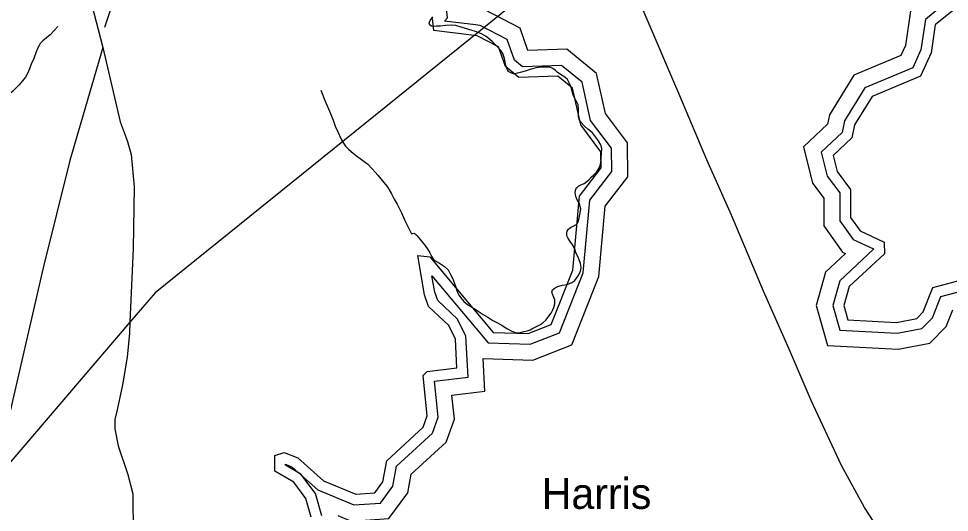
# Model space of a CAD drawing. Extents: x 2001466 to 2224147, y 644118 to 847247.
# Drawn here: x 2011540 to 2017291, y 677010 to 680062 of the extents above; entities that cross this region are included whole.
import ezdxf

# ---------------------------------------------------------------- set-up
doc = ezdxf.new("R2010")
doc.units = 0
for name, color, linetype in [('Exist Hydrographic Buffer Line', 7, 'Continuous'), ('Exist Hydrographic Lake Shore', 7, 'Continuous'), ('Exist Hydrographic Lake Shore Label', 7, 'Continuous'), ('Exist Hydrographic Misc Water Feature', 7, 'Continuous'), ('Exist Railroad Mainline', 7, 'Continuous'), ('Exist Road Non-System Type 51', 7, 'Continuous'), ('Exist Utilities Electrical Transmission Line', 7, 'Continuous')]:
    doc.layers.add(name, color=color, linetype=linetype)

msp = doc.modelspace()

# ---------------------------------------------------------------- linework, layer by layer
at = {"layer": 'Exist Hydrographic Buffer Line'}
for points in [[(2014363, 680022.7), (2014170.6, 680045.5), (2014189.4, 680065.8), (2014169, 680258.8), (2014072.9, 680448.3), (2013851.9, 680620.9), (2013847.9, 680695.5), (2013923.6, 680666.6), (2014089.2, 680466.7)], [(2017260.4, 680153.7), (2017142.7, 680057.2), (2017115.4, 679868.1), (2017064.1, 679757), (2016768.2, 679633.6), (2016643.2, 679430.8), (2016628, 679358.1), (2016498.9, 679236.6), (2016536.7, 679087.3), (2016614.4, 678984.4), (2016614.4, 678811.6), (2016695.5, 678697), (2016823, 678638.3), (2016823, 678636.6), (2016613.6, 678441.5), (2016570.9, 678288.6), (2016613.3, 678136.6), (2016968.3, 678117.6), (2017121.4, 678146.7), (2017186.1, 678212.7), (2017237.9, 678344.1), (2017449.4, 678400.7)], [(2014409.3, 677960.8), (2014717.5, 677949.8), (2014957.2, 678044.7), (2015125.2, 678468.1), (2015164.1, 678902.8), (2015303.7, 679084.4), (2015301.5, 679293.3), (2015165.5, 679474.4), (2015110.9, 679723), (2014927.8, 679872), (2014686.6, 679863.7), (2014638.7, 680002.9), (2014420.7, 680115), (2014374.6, 680120.5)], [(2017050.7, 680109.1), (2017020, 679896.3), (2016990.8, 679833.1), (2016701, 679712.2), (2016550.3, 679467.7), (2016538, 679408.5), (2016389.3, 679268.6), (2016446.1, 679043.9), (2016516, 678951.4), (2016516, 678780.3), (2016630.4, 678618.7), (2016649.8, 678609.7), (2016526.3, 678494.6), (2016468.7, 678288.7), (2016537.5, 678042), (2016974.9, 678018.7), (2017170.1, 678055.7), (2017270.4, 678158), (2017311.3, 678261.8)], [(2013413.9, 676988.9), (2013374.7, 677125.9), (2013284.4, 677246.2), (2013188.6, 677301.9), (2013188.6, 677307), (2013229.6, 677290.2), (2013387.6, 677149.2), (2013611.9, 677056.3), (2013774.8, 677066.8), (2013851.5, 677171.3), (2013875.3, 677295.4), (2014096.2, 677500.2), (2014131.9, 677597.6), (2014108.6, 677820.9), (2014316.6, 677846.4), (2014303.8, 678098.4), (2014251.5, 678204.1), (2014129.5, 678318.7), (2014110.7, 678371), (2014093.6, 678472.8), (2014441.4, 678058.1), (2014700.4, 678048.9), (2014881.4, 678120.6), (2015028.5, 678491.1), (2015068.6, 678940.1), (2015204.9, 679117.4), (2015203.5, 679260), (2015074, 679432.4), (2015022.1, 679668.3), (2014894.3, 679772.3), (2014652.3, 679764.1), (2014603.1, 679804.1), (2014558.5, 679933.5), (2014391.5, 680019.3), (2014363, 680022.7)], [(2013512.4, 676991), (2013595.4, 676956.6), (2013827, 676971.5), (2013944, 677130.9), (2013965.9, 677245.2), (2014180.5, 677444.1), (2014232.1, 677585.2), (2014216.5, 677735), (2014419.5, 677759.9), (2014409.3, 677960.8)]]:
    msp.add_lwpolyline(points, dxfattribs=at)
at = {"layer": 'Exist Hydrographic Lake Shore'}
for points in [[(2017329.1, 680125.2), (2017204, 680022.6), (2017179, 679849.3), (2017112.9, 679706.3), (2016812.9, 679581.2), (2016705.1, 679406.1), (2016688.1, 679324.4), (2016572, 679215.2), (2016597, 679116.3), (2016680.1, 679006.4), (2016680.1, 678832.5), (2016738.9, 678749.3), (2016888, 678680.6), (2016889, 678608.4), (2016671.9, 678406.1), (2016639.1, 678288.6), (2016663.9, 678199.6), (2016963.9, 678183.6), (2017088.9, 678207.3), (2017129.9, 678249.1), (2017189, 678398.9), (2017404.9, 678456.8)], [(2014355.3, 679957.6), (2014105, 679987.2), (2014097, 680062.9)], [(2013348, 676980.7), (2013315, 677096.2), (2013239.9, 677196.2), (2013123, 677264.2), (2013123, 677362.6), (2013181.1, 677381.1), (2013264.9, 677346.6), (2013423, 677205.6), (2013622.9, 677122.7), (2013740, 677130.3), (2013789.9, 677198.1), (2013814.9, 677328.9), (2014040, 677537.6), (2014065, 677605.9), (2014039, 677855.8), (2014064, 677881.6), (2014247.9, 677904.1), (2014238.9, 678081.5), (2014197.9, 678164.3), (2014073, 678281.7), (2014047, 678354.4), (2014006, 678598.1), (2014081, 678589.9), (2014472.9, 678122.7), (2014689, 678115), (2014830.9, 678171.2), (2014964, 678506.4), (2015005, 678964.9), (2015139.1, 679139.4), (2015138.1, 679237.8), (2015013, 679404.4), (2014963, 679631.9), (2014871.9, 679705.9), (2014630, 679697.7), (2014547.1, 679765), (2014505.1, 679887.2), (2014372, 679955.6), (2014355.3, 679957.6)]]:
    msp.add_lwpolyline(points, dxfattribs=at)
at = {"layer": 'Exist Hydrographic Misc Water Feature'}
for points in [[(2015112, 679115.3), (2015130.1, 679145.3), (2015138.1, 679173), (2015139.9, 679197.6), (2015142, 679231.2), (2015143.8, 679259), (2015136.4, 679281.4), (2015121.9, 679305.4), (2015103.6, 679331.2), (2015085.8, 679355.3), (2015057.7, 679378.9), (2015035.5, 679397.4), (2015015.7, 679419.1), (2015005.6, 679433.3), (2014999.7, 679455.6), (2014999.5, 679475.2), (2014999.5, 679501.5), (2014996.2, 679527.8), (2014987.4, 679549.3), (2014975.1, 679572.5), (2014965.2, 679590.8), (2014953.3, 679635.3), (2014944.1, 679660.1), (2014931, 679685), (2014915.2, 679699.2), (2014887.1, 679717.1), (2014867, 679730.6), (2014854.5, 679743.1), (2014840.7, 679754.1), (2014821.1, 679761), (2014789.1, 679762.5), (2014763, 679760.6), (2014729, 679754.7), (2014700.5, 679746.3), (2014669.7, 679737.9), (2014639.2, 679728.6), (2014605.1, 679720.3), (2014597.6, 679720.5), (2014580.9, 679726.5), (2014567, 679734.2), (2014560.8, 679744.9), (2014551, 679772.3), (2014541, 679815.9), (2014531.1, 679846.4), (2014520.9, 679863.1), (2014498.7, 679888.2), (2014464.7, 679920), (2014428.8, 679951.9), (2014400.7, 679968.1), (2014362.8, 679982), (2014320.7, 679994.3), (2014280.7, 680005.8), (2014240.6, 680019.7), (2014214.3, 680021.9), (2014176.6, 680019.4), (2014146.6, 680015.9), (2014122.7, 680014), (2014104.8, 680013.5), (2014090.7, 680015.4), (2014080.8, 680021.3), (2014076.7, 680033.7), (2014082.5, 680049.2), (2014098.5, 680073.4)], [(2011781.6, 680012.3), (2011759.6, 679988.1), (2011733.6, 679962.4), (2011711.7, 679943.9), (2011689.7, 679923.9), (2011673.5, 679907.9), (2011665.7, 679895.7), (2011657.7, 679881.9), (2011647.7, 679855.8), (2011633.7, 679815.2), (2011617.9, 679780.2), (2011606, 679751.7), (2011594, 679721.6), (2011582.1, 679699.7), (2011564, 679676.3), (2011542.1, 679652.2), (2011522.4, 679632), (2011502.3, 679611.9), (2011486.1, 679597.5), (2011466.2, 679579.8), (2011450.2, 679563.8), (2011440.4, 679551.6), (2011432.4, 679543.6), (2011426.6, 679538)], [(2013406, 679619.2), (2013434.1, 679551.3), (2013459.9, 679489.3), (2013470.2, 679465.3), (2013482.3, 679433.1), (2013496.2, 679397.5), (2013510.4, 679365.2), (2013532.3, 679315.6), (2013546.5, 679291.5), (2013560.4, 679273.1), (2013580.7, 679253.1), (2013606.5, 679229.6), (2013626.4, 679213.5), (2013649.6, 679196.7), (2013682.6, 679171.5), (2013694.5, 679163.8), (2013724.9, 679133.6), (2013742.7, 679111.9), (2013758.7, 679093.6), (2013778.8, 679071.9), (2013796.8, 679049.3), (2013806.7, 679036), (2013820.8, 679017.7), (2013843, 678979.5), (2013860.8, 678946.3), (2013878.8, 678914), (2013905.1, 678861.8), (2013927, 678813.7), (2013948.8, 678769), (2013967, 678730.9)], [(2013967, 678730.9), (2013981, 678735.5), (2013989, 678731.3), (2014002.9, 678719.5), (2014028.9, 678685.3), (2014048.8, 678661.1), (2014068.9, 678635.3), (2014081, 678613.8), (2014092.9, 678589.7), (2014103.2, 678573.9), (2014121, 678559.6), (2014141.1, 678549.4), (2014171, 678529.9), (2014193.2, 678509.8), (2014211.2, 678475.8), (2014219.8, 678456.7), (2014227.4, 678441.8), (2014239.3, 678407.9), (2014243.4, 678393.9), (2014247.5, 678381.5), (2014251.4, 678368.3), (2014260, 678351.7), (2014271.5, 678335.9), (2014291.4, 678314.1), (2014313.6, 678295.6), (2014349.6, 678271.9), (2014379.6, 678254.2), (2014409.5, 678233.8), (2014439.7, 678216), (2014469.8, 678196.5), (2014490.3, 678185.5), (2014525.6, 678166.7), (2014539.9, 678156.5), (2014559.8, 678144.7), (2014587.7, 678130.2), (2014609.9, 678122.3), (2014629.7, 678120.3), (2014641.8, 678122.5), (2014663.8, 678127), (2014681.8, 678132.4), (2014699.9, 678138.5), (2014711.8, 678144.8), (2014759.8, 678168.4), (2014779.6, 678182), (2014797.7, 678198.9), (2014815.5, 678223.1), (2014829.7, 678240.9), (2014841.6, 678261.1), (2014847.3, 678276.7), (2014853.3, 678298.7), (2014853.5, 678323.3), (2014847.5, 678338.9), (2014841.6, 678354.6), (2014833.4, 678371.2), (2014839.3, 678385.1), (2014849.4, 678394.7), (2014861.3, 678401), (2014877.4, 678408.9), (2014899.2, 678413.4), (2014929.3, 678419.3), (2014957.2, 678431.1), (2014977.1, 678443), (2014997.2, 678471.3), (2015011.1, 678498.8), (2015015, 678523.4), (2015011.1, 678548.9), (2015002.9, 678571.2), (2014994.9, 678591.1), (2014984.9, 678611), (2014979, 678630.8), (2014965, 678661.4), (2014946.8, 678684.7), (2014932.8, 678707.2), (2014926.7, 678718.8), (2014926.7, 678735.2), (2014928.7, 678747.5), (2014936.7, 678761.2), (2014950.7, 678770.8), (2014970.5, 678781), (2014982.6, 678787.3), (2014992.5, 678797), (2014996.6, 678805.1), (2014998.4, 678809.2), (2015007, 678851.7), (2015012.6, 678885.2), (2015010.3, 678900.8), (2015002.5, 678923.1), (2014992.3, 678937.3), (2014982.4, 678961.3), (2014978.3, 678986.8), (2014982.2, 679007.2), (2014989.4, 679016.1), (2015002.1, 679027.3), (2015010.3, 679032.9), (2015034.3, 679043), (2015050.3, 679055), (2015062.2, 679065.4), (2015080, 679083.2), (2015092.1, 679093.5), (2015112, 679115.3)]]:
    msp.add_lwpolyline(points, dxfattribs=at)
at = {"layer": 'Exist Railroad Mainline'}
msp.add_lwpolyline([(2016912, 676816.5), (2016766.7, 677040.2), (2016623.8, 677299.9), (2016436.8, 677702.2), (2016300.6, 678017.8), (2016142.9, 678377.8), (2015944.4, 678846), (2015792.6, 679187.9), (2015625.4, 679583.8), (2015397.8, 680114.6), (2015185.6, 680595.1), (2015174.6, 680618.2), (2014980.9, 681025.5), (2014822.4, 681323.4), (2014589.4, 681740.1), (2014324.6, 682161.3), (2014136.7, 682458.4)], dxfattribs=at)
at = {"layer": 'Exist Road Non-System Type 51'}
for points in [[(2011599.3, 681514.6), (2011662.5, 681347), (2011788.9, 680898.1), (2011905.8, 680480.8), (2012060.6, 679883.3)], [(2012060.6, 679883.3), (2011855.2, 679184.6), (2011690.9, 678520.7), (2011463.4, 677528), (2011425.5, 677313), (2011427.3, 677250.4)], [(2012060.6, 679883.3), (2012167.8, 679424.7), (2012210.2, 679308.2), (2012235.3, 679221.9), (2012252.8, 679021.7), (2012248.3, 678641.8), (2012227.1, 678184.7)], [(2012227.1, 678184.7), (2012224, 678118.1), (2012210.2, 677970.3), (2012182.1, 677798.5), (2012148.3, 677643), (2012133.5, 677583.1), (2012135, 677527.2), (2012155.6, 677420.8), (2012215.4, 677244.2), (2012246, 677123.8), (2012247.1, 676873.9), (2012247.2, 676711.9), (2012258.5, 676657.7), (2012294, 676623.4), (2012384, 676614.3), (2012493.8, 676604.9), (2012603.6, 676583.7), (2012671.4, 676560.9), (2012723.1, 676536.2), (2012774.8, 676511.6)]]:
    msp.add_lwpolyline(points, dxfattribs=at)
at = {"layer": 'Exist Utilities Electrical Transmission Line'}
for p, q in [((2013356.3, 683873), (2012070.1, 680006.6)), ((2012227.1, 678184.7), (2008754.8, 674128.4))]:
    msp.add_line(p, q, dxfattribs=at)
msp.add_lwpolyline([(2018161.4, 683064.2), (2017435.4, 682442.9), (2012383.7, 678367.6), (2012227.1, 678184.7)], dxfattribs=at)

# ---------------------------------------------------------------- texts
at = {"layer": 'Exist Hydrographic Lake Shore Label'}
msp.add_text('Harris', height=190, dxfattribs=at).set_placement((2014771.9, 677031.7))

doc.saveas('drawing.dxf')
